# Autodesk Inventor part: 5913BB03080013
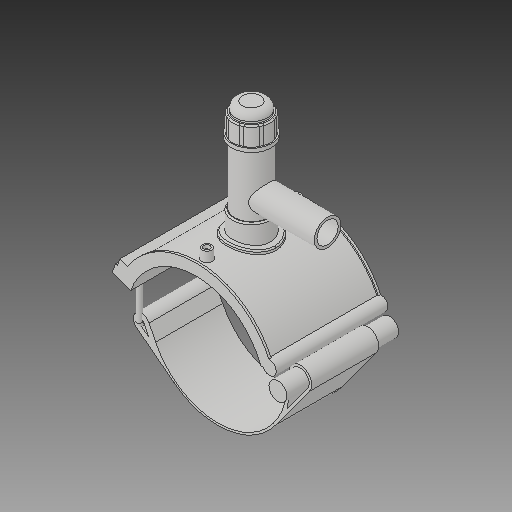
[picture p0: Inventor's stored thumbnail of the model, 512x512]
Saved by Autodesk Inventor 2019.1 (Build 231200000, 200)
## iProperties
Created: 2017-07
Part Number: 5913BB03080013
Material: Generic
Description: PLASSON HIGH VOLUME TAPPING TEE 8''IPS x 1 1/4''IPS
Document SubType Name: Modeling
Designer: KIM
Mass: 1712.7 g
Surface Area: 2671.49 cm^2
Volume: 1712.7 cm^3
Density: 1 g/cm^3
Appearance: Default
Author: KIM
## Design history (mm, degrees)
derived "5913B.ipt"
feature "Solid1::5913B.ipt"
feature "Solid2::5913B.ipt"
feature "Solid4::5913B.ipt"
feature "Solid5::5913B.ipt"
tag "TaggingFeature1"
body "Solid1"
body "Solid2"
other parameters: "d0" = 218.7, "d2" = 449.58, "d3" = 54.675, "d4" = 176.022, "d5" = 0, "d6" = 0.1, "d8" = 0, "d40" = 129.64536, "d41" = 76.545, "d43" = 0, "d45" = 0, "d47" = 230.2722, "d78" = 139.35, "d79" = 15, "d80" = 70.4088, "d82" = 5 deg, "d84" = 4, "d85" = 14, "d86" = 0, "d87" = 3, "d88" = 0, "d96" = 254.30436, "d97" = 3.52044, "d98" = 0, "d102" = 2.187, "d120" = 140 deg, "d121" = 24.228, "d122" = 20 deg, "d123" = 623.295, "d124" = 149.5908, "d126" = 0, "d153" = 176.022, "d154" = 0, "d159" = 6.1236, "d162" = 105.6132, "d163" = 0, "d164" = 109.35, "d169" = 4.0905, "d170" = 9.1854, "d172" = 0, "d173" = 1, "d175" = 109.35, "d176" = 20 deg, "d177" = 15.309, "d178" = 30.618, "d180" = 0, "d183" = 12.2472, "d184" = 12.2472, "d187" = 124.659, "d188" = 9.1854, "d189" = 15.309, "d190" = 0, "d191" = 186.9885, "d193" = 7.8732, "d194" = 3.9366, "d195" = 90 deg, "d197" = 0, "d199" = 0, "d200" = 15.309, "d202" = 0, "d203" = 194.818, "d204" = 59.62855, "d205" = 43.93683, "d206" = 53.35186, "d207" = 146.1135, "d208" = 151.95804, "d209" = 181.18074, "d210" = 53.97953, "d211" = 62.7669, "d212" = 50.21352, "d213" = 48.492, "d216" = 0, "d217" = 21.87, "d218" = 10.935, "d219" = 2.187, "d222" = 218.7, "d224" = 0, "d230" = 2.187, "d257" = 184.28, "d258" = 119.888, "d259" = 33.68, "d260" = 42.1, "d263" = 179.832, "d265" = 0, "d267" = 13.00006, "d268" = 2.60001, "d269" = 2.60001, "d271" = 2.60001, "d273" = 0, "d274" = 23.56194, "d275" = 174.96, "d277" = 87.48, "d278" = 349.92, "d280" = 0, "d281" = 218.7, "d283" = 0, "d285" = 0, "d290" = 21.87, "d291" = 28.431, "d293" = 120.285, "d294" = 112.6305, "d296" = 32.805, "d297" = 26.244, "d_" = 218.7, "B_" = 179.832, "L_" = 176.022, "d_t" = 6, "H_2" = 194.818, "H_1" = 74.93, "d_1" = 42.1, "H_" = 119.888, "d1" = 249.318, "d192" = 7.8732
